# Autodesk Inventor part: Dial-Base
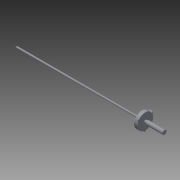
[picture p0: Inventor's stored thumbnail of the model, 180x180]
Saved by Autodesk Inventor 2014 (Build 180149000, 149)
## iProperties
Shininess: 64.0
Length Units: 11272
Angle Units: 11279
Time Units: 11290
Mass Units: 11286
Length Display Precision: 3
Angle Display Precision: 2
Compacted: True
Created: 2001-11
Part Number: Dial-Base
Document SubType Name: Modeling
Designer: Autodesk, Inc.
Mass: 1.78334 g
Surface Area: 19.6041 cm^2
Volume: 1.78334 cm^3
Density: 1 g/cm^3
Material: Generic
Appearance: Default
Density: 0.0
Volumn: 0.0
Area: 0.0
PropertySet Name: Model Information
Control State: 0
Master: False
Checked Out: False
Author: Autodesk, Inc.
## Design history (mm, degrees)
sketch "Sketch1"
  geometry: L1 (150.134, 1.855)-(150.134, 2.363); L2 (147.848, 1.601)-(149.88, 1.601); L3 (147.594, 1.855)-(147.594, 8.903); L4 (143.657, 8.903)-(147.594, 8.903); L5 (143.657, 0.979)-(143.657, 8.903); L6 (1.649, 0.979)-(143.657, 0.979); L7 (0, 0)-(1.649, 0.979); L8 (169.311, 0)-(169.311, 2.363); L9 (150.134, 2.363)-(169.311, 2.363); L10 (0, 0)-(169.311, 0); A1 r 0.254 centre (149.88, 1.855) between (149.88, 1.601) and (150.134, 1.855); A2 r 0.254 centre (147.848, 1.855) between (147.594, 1.855) and (147.848, 1.601); 1 further point
  constraints: 20 end point, 4 horizontal, 4 point on circle, 4 tangent, 4 vertical, 2 centre point, 1 coincident, 1 equal radius, 1 parallel
  dimensions: "d11" = 1.95865 diameter of L6 L10; "d12" = 17.80607 diameter of L4 L10; "d13" = 4.72507 diameter of L9 L10; "d14" = 19.177 distance of L1.end L8.end; "d15" = 0.254 radius of A1; "d16" = 2.54 distance between parallel lines of L1 L3; "d17" = 3.937 distance of L4.start L3.end; "d18" = 142.00729 distance of L6.start L5.start; "d19" = 30.6993 deg angle of L10 L7; "d20" = 3.20107 diameter of L2 L10
revolve "RevolutionFull1" sketch "Sketch1" stored, may be unused: angle "d0" = 360 deg
sketch "Sketch2"
  geometry: L1 (9.094, 4.56)-(7.989, 3.93); L2 (8.551, 5.511)-(7.446, 4.881); L3 (0, -12.464)-(0, 12.464) reference; A1 r 8.903 centre (0, 0) between (7.446, 4.881) and (7.989, 3.93) reference; A2 r 10.173 centre (0, 0) between (9.094, 4.56) and (8.551, 5.511)
  constraints: 4 end point, 4 point on circle, 2 parallel, 1 centre point, 1 coincident
  dimensions: "d21" = 60.2814 deg angle of L2 L3; "d23" = 1.09507 distance between parallel lines of L1 L2; "d24" = 1.27215 distance of L2.start L2.end
extrude "ExtrusionToPlane1" join sketch "Sketch2" stored distance "d5" = 3.302; taper "d6" = 0 deg
pattern_circular "Circular Pattern1" dims angle "d27" = 360 deg
body "Solid1"
other parameters: "d1" = 0, "d2" = 0, "d3" = 0, "d4" = 0
